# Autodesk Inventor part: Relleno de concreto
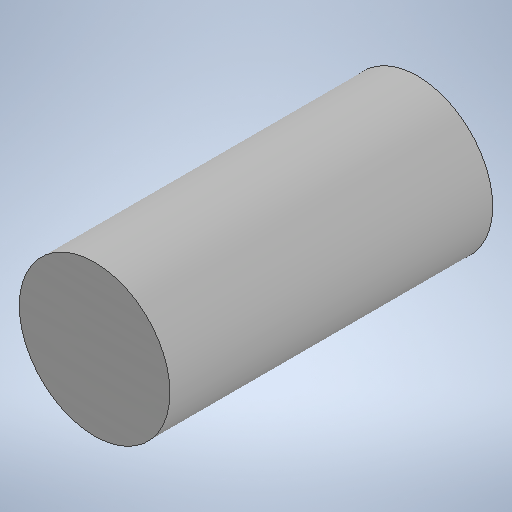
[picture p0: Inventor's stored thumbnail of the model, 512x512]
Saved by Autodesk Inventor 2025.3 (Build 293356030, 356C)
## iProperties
Created: 2025-09
Part Number: Relleno de concreto
Material: Genérico
Document SubType Name: Modeling
Designer: User
Density: 1 g/cm^3
Appearance: Valor por defecto
Author: User
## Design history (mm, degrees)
sketch "Boceto1"
  geometry: C1 r 70 at (0, 0); 1 further point
  constraints: 1 centre point, 1 coincident
  dimensions: "d0" = 140 diameter of C1
extrude "Extrusión1" new body sketch "Boceto1" stored distance "d1" = 300; taper "d2" = 0 deg
node "Sólido1"
node "Acabados"
node "Finish2" dims "Finish2_Area" = 16273.44995
